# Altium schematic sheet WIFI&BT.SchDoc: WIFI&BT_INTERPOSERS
size A3; Author: P.A.; CompanyName: STMicroelectronics; Organization: Microcontrollers Division; Address1: 12, Rue Jules HOROWITZ; Address2: 38019 Grenoble; Address3: FRANCE; DocumentNumber: 13; Revision: C; SheetNumber: 13; SheetTotal: 16; Project: STM32L4S5AII6_IOT_V2; PageSetup: Record=PageOptions¦CenterHorizontal=True¦CenterVertical=True¦PrintScale=1.00¦XCorrection=1.00¦YCorrection=1.00¦PrintKind=1¦BorderSize=5000000¦LeftOffset=0¦BottomOffset=0¦Orientation=2¦PaperLength=1000¦PaperWidth=1000¦Scale=100¦PaperSource=7¦PrintQuality=-3¦MediaType=1¦DitherType=10¦PrintScaleMode=1¦PaperKind=Letter¦PaperIndex=1
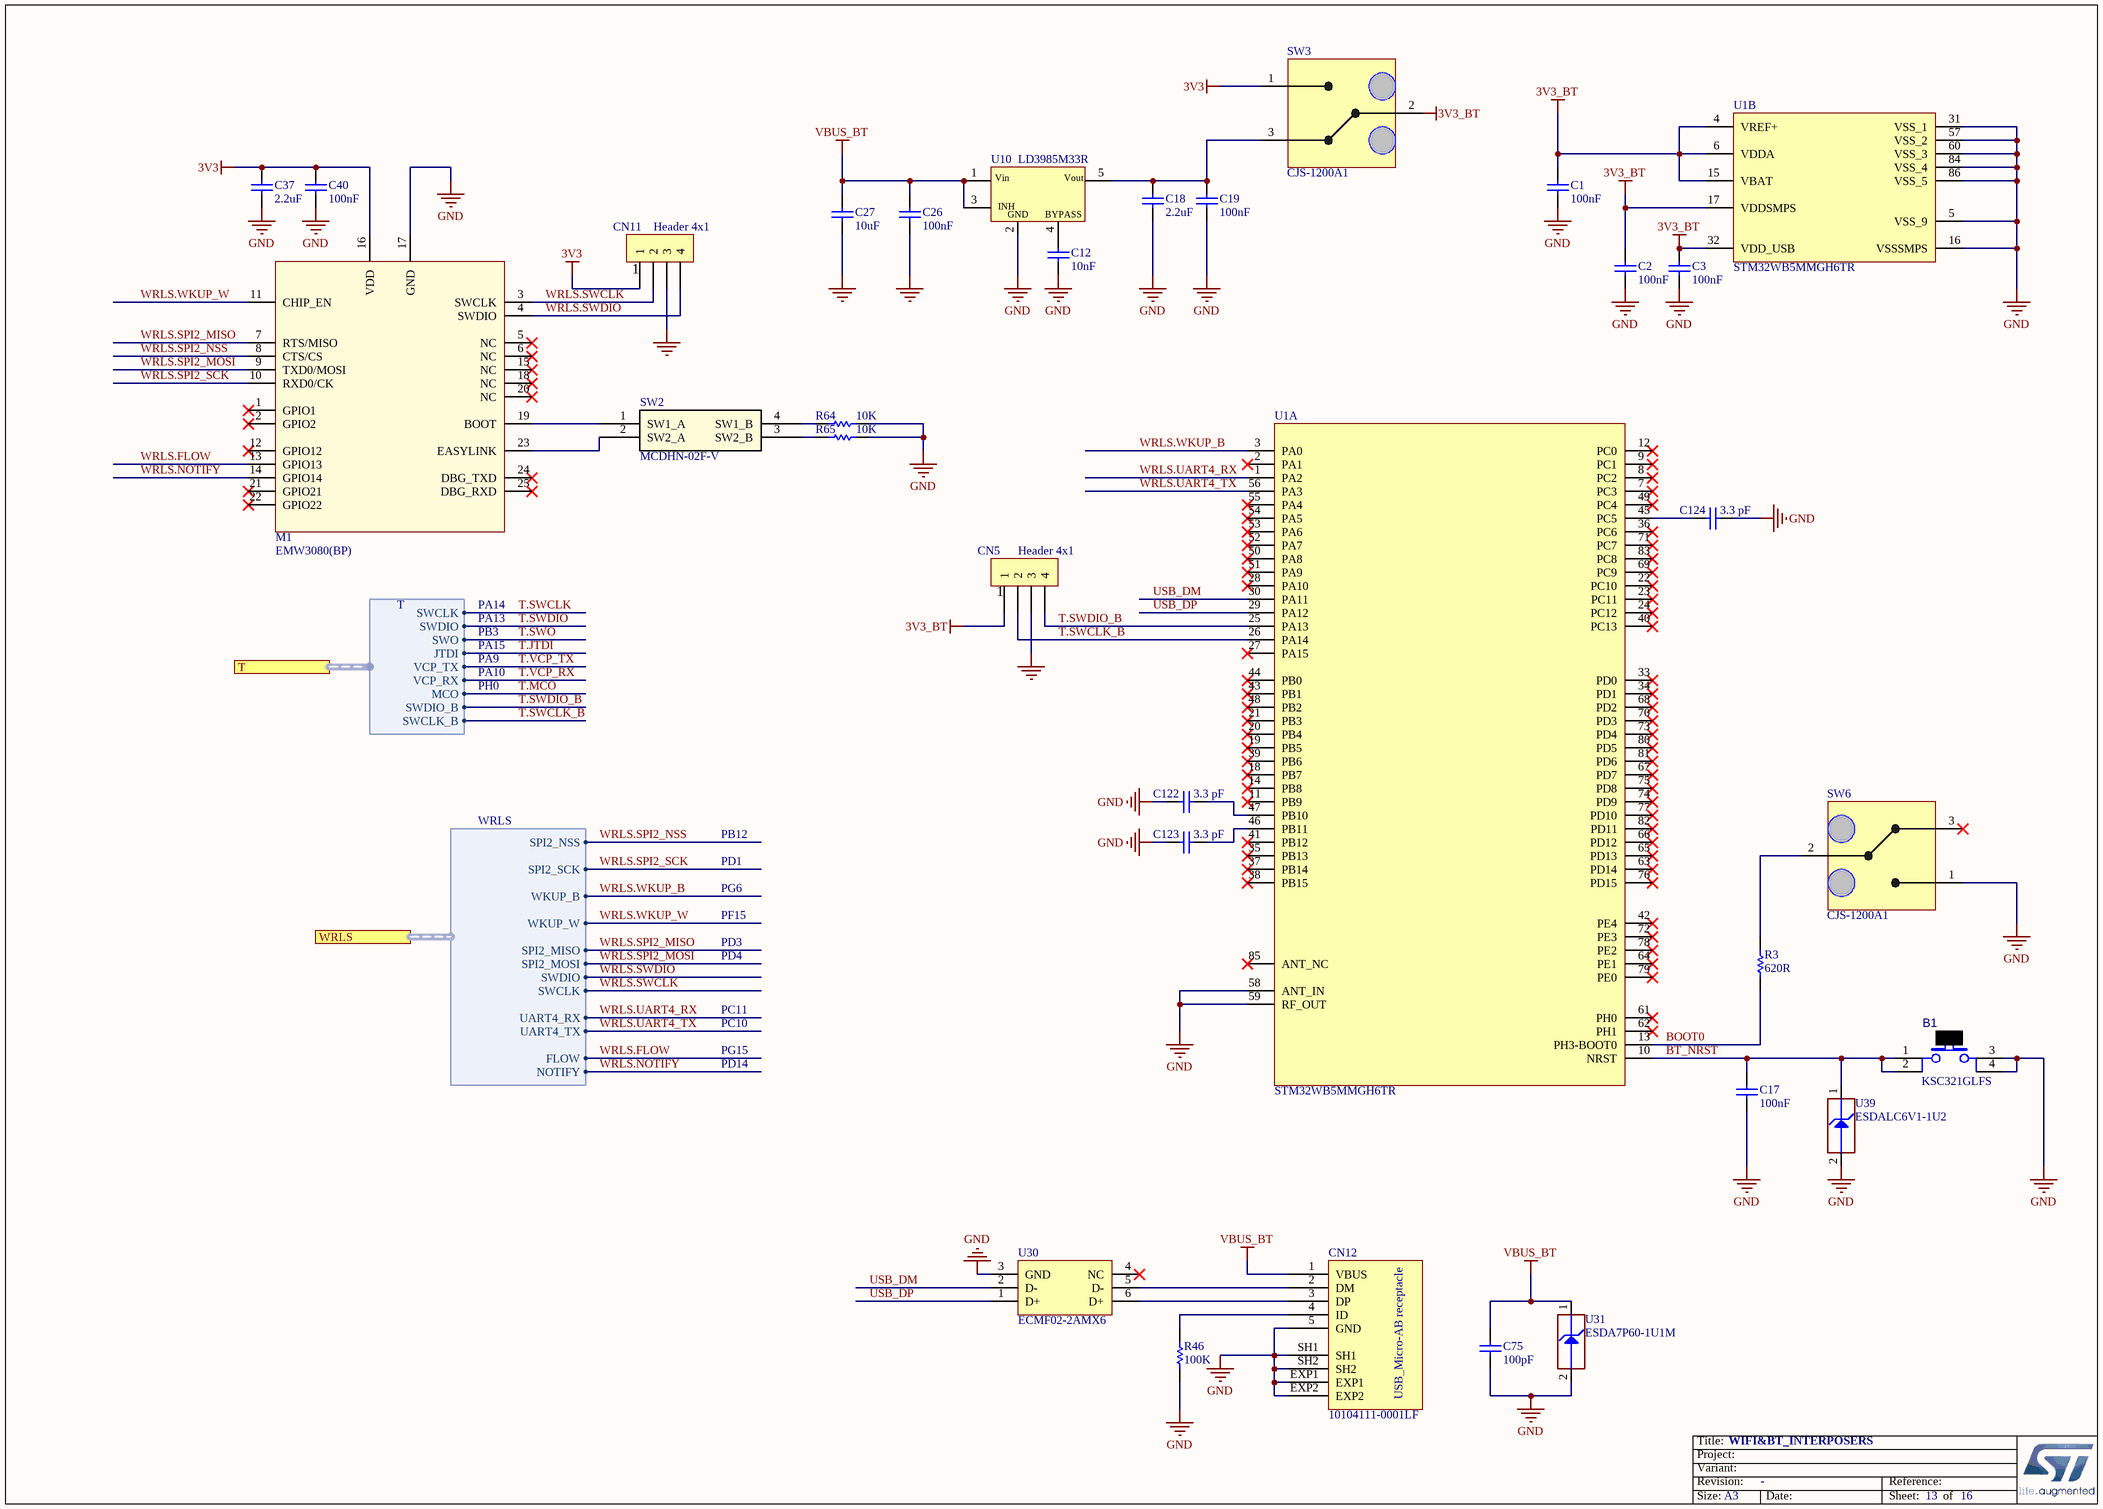
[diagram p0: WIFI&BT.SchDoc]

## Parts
(Parts that share a designator on the sheet are numbered #1, #2 ... from top to bottom, then left to right.)
B1  value KSC321GLFS  [SWI_C&K_KSC321GLFS_BLACK]  (hidden comment: SW_BLACK_KSC321GLFS)
C1  value 100nF  [C0402]
C2  value 100nF  [C0402]
C3  value 100nF  [C0402]
C12  value 10nF  [C0402]  (hidden comment: Capacitor)
C17  value 100nF  [C0402]
C18  value 2.2uF  [C0603]  (hidden comment: Capacitor)
C19  value 100nF  [C0402]  (hidden comment: Capacitor)
C26  value 100nF  [C0402]  (hidden comment: Capacitor)
C27  value 10uF  [C0603]  (hidden comment: Capacitor)
C37  value 2.2uF  [C0603]  (hidden comment: Capacitor)
C40  value 100nF  [C0402]  (hidden comment: Capacitor)
C75  value 100pF  [C0402]
C122  value 3.3 pF  [C0201_H0P3]  (hidden comment: Capacitor)
C123  value 3.3 pF  [C0201_H0P3]  (hidden comment: Capacitor)
C124  value 3.3 pF  [C0201_H0P3]  (hidden comment: Capacitor)
CN5  Header 4x1  [CON_SAMTEC_TSW-104-07-G-S]
CN11  Header 4x1  [CON_SAMTEC_TSW-104-07-G-S]
CN12  value 10104111-0001LF  [CON_USBMICROAB_FCI_10104111-0001LF]  (hidden comment: USB_uAB_10104111-0001LF)
M1  EMW3080(BP)  [MOD_WIFI_MXCHIP_EMW3080-BP]
R3  value 620R  [R0402]  (hidden comment: Resistor)
R46  value 100K  [R0402]  (hidden comment: Resistor)
R64  value 10K  [R0603]
R65  value 10K  [R0603]
SW2  value MCDHN-02F-V  [SWI_MULTICOMP_MCDHN-02F-V_4P]  (hidden comment: SWITCH_2WAY)
SW3  CJS-1200A1  [SWI_CJS-1200A1]
SW6  CJS-1200A1  [SWI_CJS-1200A1]
U1#1  STM32WB5MMGH6TR  [MOD_DORY_STM_86P_7P3X11_H1P342]  (part B of 2)
U1#2  STM32WB5MMGH6TR  [MOD_DORY_STM_86P_7P3X11_H1P342]  (part A of 2)
U10  LD3985M33R  [REG_SOT23-5L]
U30  ECMF02-2AMX6  [ESD_QFN-6L_1P7X1P5_P050]
U31  value ESDA7P60-1U1M  [ESD_QFN2_1P6X1_P125]  (hidden comment: ESD-TRANSIL)
U39  value ESDALC6V1-1U2  [ESD_ST0201]  (hidden comment: ESD-TRANSIL)

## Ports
T (harness T), WRLS (harness WRLS)

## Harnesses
WRLS: WKUP_B, WKUP_W, SPI2_NSS, SPI2_SCK, SPI2_MISO, SPI2_MOSI, SWDIO, SWCLK, UART4_RX, UART4_TX, FLOW, NOTIFY
T: SWCLK, SWDIO, SWO, JTDI, VCP_RX, VCP_TX, MCO, SWDIO_B, SWCLK_B

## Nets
3V3: C37.2 C40.2 CN11.1 M1.16(VDD) SW3.1
3V3_BT: C1.2 C2.2 C3.2 CN5.1 SW3.2 U1#1.4(VREF+) U1#1.6(VDDA) U1#1.15(VBAT) U1#1.17(VDDSMPS) U1#1.32(VDD_USB)
GND: B1.3 B1.4 C1.1 C2.1 C3.1 C12.2 C17.1 C18.1 C19.1 C26.1 C27.1 C37.1 C40.1 C75.1 C122.1 C123.1 C124.2 CN5.3 CN11.3 CN12.5(GND) CN12.EXP1 CN12.EXP2 CN12.SH1 CN12.SH2 M1.17(GND) R46.1 R64.2 R65.2 SW6.1 U1#1.5(VSS_9) U1#1.16(VSSSMPS) U1#1.31(VSS_1) U1#1.57(VSS_2) U1#1.60(VSS_3) U1#1.84(VSS_4) U1#1.86(VSS_5) U1#2.58(ANT_IN) U1#2.59(RF_OUT) U10.2(GND) U30.3(GND) U31.2(GND) U39.2(GND)
VBUS_BT: C26.2 C27.2 C75.2 CN12.1(VBUS) U10.1(Vin) U10.3(CE) U31.1(IO1)
BOOT0: R3.1 U1#2.13(PH3-BOOT0)
BT_NRST: B1.1 B1.2 C17.2 U1#2.10(NRST) U39.1(IO1)
T.SWCLK_B: CN5.2 U1#2.26(PA14) ; port T.SWCLK_B
T.SWDIO_B: CN5.4 U1#2.25(PA13) ; port T.SWDIO_B
USB_DM: U1#2.30(PA11) U30.2(D-)
USB_DP: U1#2.29(PA12) U30.1(D+)
WRLS.FLOW: M1.13(GPIO13) ; port WRLS.FLOW
WRLS.NOTIFY: M1.14(GPIO14) ; port WRLS.NOTIFY
WRLS.SPI2_MISO: M1.7(RTS/MISO) ; port WRLS.SPI2_MISO
WRLS.SPI2_MOSI: M1.9(TXD0/MOSI) ; port WRLS.SPI2_MOSI
WRLS.SPI2_NSS: M1.8(CTS/CS) ; port WRLS.SPI2_NSS
WRLS.SPI2_SCK: M1.10(RXD0/CK) ; port WRLS.SPI2_SCK
WRLS.SWCLK: CN11.2 M1.3(SWCLK) ; port WRLS.SWCLK
WRLS.SWDIO: CN11.4 M1.4(SWDIO) ; port WRLS.SWDIO
WRLS.UART4_RX: U1#2.1(PA2) ; port WRLS.UART4_RX
WRLS.UART4_TX: U1#2.56(PA3) ; port WRLS.UART4_TX
WRLS.WKUP_B: U1#2.3(PA0) ; port WRLS.WKUP_B
WRLS.WKUP_W: M1.11(CHIP_EN) ; port WRLS.WKUP_W
NetC12_1: C12.1 U10.4(BYPASS)
NetC18_2: C18.2 C19.2 SW3.3 U10.5(Vout)
NetC122_2: C122.2 U1#2.47(PB10)
NetC123_2: C123.2 U1#2.46(PB11)
NetC124_1: C124.1 U1#2.45(PC5)
NetCN12_2: CN12.2(DM) U30.5(D-)
NetCN12_3: CN12.3(DP) U30.6(D+)
NetCN12_4: CN12.4(ID) R46.2
NetM1_19: M1.19(BOOT) SW2.1(SW1_A)
NetM1_23: M1.23(EASYLINK) SW2.2(SW2_A)
NetR3_2: R3.2 SW6.2
NetR64_1: R64.1 SW2.4(SW1_B)
NetR65_1: R65.1 SW2.3(SW2_B)

Not connected (* = marked no-connect by the designer): M1 1(GPIO1)* 2(GPIO2)* 5(NC)* 6(NC)* 12(GPIO12)* 15(NC)* 18(NC)* 20(NC)* 21(GPIO21)* 22(GPIO22)* 24(DBG_TXD)* 25(DBG_RXD)*; SW6 3*; U1#2 2(PA1)* 7(PC3)* 8(PC2)* 9(PC1)* 11(PB9)* 12(PC0)* 14(PB8)* 18(PB7)* 19(PB5)* 20(PB4)* 21(PB3)* 22(PC10)* 23(PC11)* 24(PC12)* 27(PA15)* 28(PA10)* 33(PD0)* 34(PD1)* 35(PB13)* 36(PC6)* 37(PB14)* 38(PB15)* 39(PB6)* 40(PC13)* 41(PB12)* 42(PE4)* 43(PB1)* 44(PB0)* 48(PB2)* 49(PC4)* 50(PA8)* 51(PA9)* 52(PA7)* 53(PA6)* 54(PA5)* 55(PA4)* 61(PH0)* 62(PH1)* 63(PD14)* 64(PE1)* 65(PD13)* 66(PD12)* 67(PD7)* 68(PD2)* 69(PC9)* 70(PD3)* 71(PC7)* 72(PE3)* 73(PD4)* 74(PD9)* 75(PD8)* 76(PD15)* 77(PD10)* 78(PE2)* 79(PE0)* 80(PD5)* 81(PD6)* 82(PD11)* 83(PC8)* 85(ANT_NC)*; U30 4(NC)*

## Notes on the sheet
- (near CN11) 1
- PA14
- PA13
- PB3
- PA15
- (near CN5) 1
- PA10
- PA9
- PH0
- PB12
- PD1
- PF15
- PG6
- PD4
- PD3
- PC10
- PC11
- PG15
- PD14

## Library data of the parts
B1 = MCD-00175: Switch HW BLACK High3.5mm 2Newtons; Part_Type: Misc; Manufacturer: C&K; Provided_By: SUBCO; Initial_Board_Reference: MB1274
C1-C3 C17 = MCD-00006: Capacitor, MLCC, 100nF, 16V, X7R, 10%, 0402, T=0.5mm; Manufacturer_Part_Number: CC0402KRX7R7BB104; Manufacturer: YAGEO; Alternate_Manufacturer_Part_Number: GCM155R71C104KA55D; Alternate_Manufacturer: MURATA; Provided_By: SUBCO; ECCN_US: EAR99; ECCN_EU: NEC
C12 = MCD-00011: Capacitor,10nF,16V,X7R,10%,0402,YAGEO; Manufacturer_Part_Number: CC0402KRX7R7BB103; Provided_By: Subcon
C18 = MCD-00012: Capacitor,2.2uF,10V, X5R,10%,0603,YAGEO; Manufacturer_Part_Number: CC0603KRX5R6BB225; Alternate_Manufacturer_Part_Number: C0603C225K8PACTU; Alternate_Manufacturer: KEMET; Provided_By: Subcon
C19 C26 = MCD-00006: Capacitor,100nF,16V,X7R,10%,0402,YAGEO; Manufacturer_Part_Number: CC0402KRX7R7BB104; Provided_By: Subcon
C27 = MCD-00243: Capacitor,10uF,6V3,X5R,10%,0603,YAGEO; Manufacturer_Part_Number: CC0603KRX5R5BB106; Provided_By: Subcon
C37 = MCD-00012: Capacitor, MLCC, 2.2uF, 10V, X5R, 10%, 0603, T=0,8mm; Manufacturer_Part_Number: CC0603KRX5R6BB225; Manufacturer: YAGEO; Alternate_Manufacturer_Part_Number: C0603C225K8PACTU; Alternate_Manufacturer: KEMET; Provided_By: SUBCO
C40 = MCD-00006: Capacitor, MLCC, 100nF, 16V, X7R, 10%, 0402, T=0.5mm; Manufacturer_Part_Number: CC0402KRX7R7BB104; Manufacturer: YAGEO; Alternate_Manufacturer_Part_Number: GCM155R71C104KA55D; Alternate_Manufacturer: MURATA; ECCN_US: EAR99; ECCN_EU: NEC; Provided_By: SUBCO
C75 = MCD-00205: Capacitor, MLCC, 100pF, 50V, NPO, 5%, 0402, T=0,5mm; Manufacturer_Part_Number: CC0402JRNPO9BN101; Manufacturer: YAGEO; Provided_By: Subcon; Initial_Board_Reference: MB1361
C122-C124 = MCD-02284: Capacitor, MLCC, 3.3pF, 50V, NPO, +-0.05pF, 0201, T=0.3mm".; Part_Preference: Recommended; Manufacturer: MURATA; Manufacturer_Part_Number: GRM0335C2A3R3WA01J
CN5 CN11 = MCD-00029: Header, 4x1, 2,54mm, VR, TH, Height 5.84mm/2.54mm; Manufacturer_Part_Number: TSW-104-07-x-S; Manufacturer: SAMTEC; Part_Type: Connector; Provided_By: Subcon; Initial_Board_Reference: MB1274
CN12 = MCD-01075: USB, micro AB receptacle,10104111-0001LF; Part_Type: Connector; Manufacturer: FCI; Provided_By: SUBCO
M1 = MCD-01500: Wi-Fi module 33x18mm, UART-SPI interface; Part_Type: IC; Manufacturer: MXCHIP; Provided_By: SUBCO
R3 = MCD-00499: Resistor, 620R, 0402, +/-1%, 1/16W; Part_Preference: Recommended; Manufacturer: YAGEO; Manufacturer_Part_Number: RC0402FR-07620RL; Component_Country_Of_Origin: China; ShowFields: YES; ID: 2781
R46 = MCD-00059: Resistor,100K,0402,1%,1/16W; Manufacturer_Part_Number: RC0402FR-07100KL; Manufacturer: YAGEO; Alternate_Manufacturer_Part_Number: RT0402FRE07100KL; ECCN_US: EAR99; ECCN_EU: NEC; Provided_By: SUBCO
R64 R65 = MCD-00220: Resistor,10K,0603,1%,1/10W; Manufacturer_Part_Number: RC0603FR-0710KL; Manufacturer: YAGEO; Provided_By: Subcon; Initial_Board_Reference: MB1319
SW2 = MCD-02105: DIP Switch Slide Type x2 poles 25mA 24VDC 100mR SMD; Part_Type: Misc; Manufacturer: MULTICOMP; Provided_By: SUBCO
SW3 SW6 = MCD-02279: SLIDE SWITCHE (SMD) serie CJS; Part_Preference: Recommended; Part_Type: Misc; Manufacturer: NIDEC Copal
U1#1 = MCD-01965: STM32 module BLE oriented  based on DORY STM32WB55; Part_Type: Misc; Manufacturer: STMICROELECTRONICS
U1#2 = MCD-01965: STM32 BLE module based on STM32WB55; Part_Type: Misc; Manufacturer: STMICROELECTRONICS; Part_Preference: Recommended; Manufacturer_HQ_COO: EU; Component_Country_Of_Origin: Taiwan; ShowFields: YES; ID: 4065
U10 = MCD-00086: Ultra low drop-low noise BiCMOS voltage, regulators low ESR capacitors compatible; Manufacturer: STM; ECCN_US: EAR99; ECCN_EU: NEC
U30 = MCD-00649: Common mode filter with ESD protection for USB 2.0 interface; Part_Type: Diode; Manufacturer: STMICROELECTRONICS; BMS_Part_Number: 9151138; ECCN_US: EAR99; ECCN_EU: NEC; Provided_By: SUBCO with ST control
U31 = MCD-00251: High power transient voltage suppressor, 7V breakdown; Part_Type: Diode; Manufacturer: STMICROELECTRONICS; BMS_Part_Number: 9179042; ECCN_US: EAR99; ECCN_EU: NEC; Provided_By: SUBCO with ST control
U39 = MCD-00170: ESD protection 6V1; BMS_Part_Number: 9151132; Part_Preference: Recommended; Part_Type: Diode; Manufacturer: STMICROELECTRONICS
